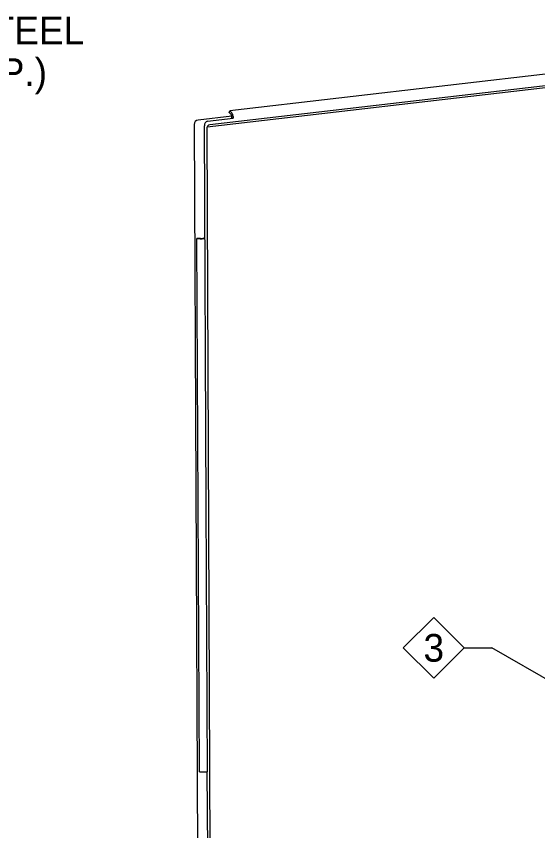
# Model space of a CAD drawing. Extents: x 99862 to 104211, y 98939 to 102076.
# Drawn here: x 101939.9 to 102241.1, y 100806.7 to 101277.4 of the extents above; entities that cross this region are included whole.
import ezdxf

# ---------------------------------------------------------------- set-up
doc = ezdxf.new("R2010")
doc.units = 0
for name, color, linetype in [('Level 15', 7, 'Continuous'), ('Level 20', 7, 'Continuous'), ('Level 3', 7, 'Continuous')]:
    doc.layers.add(name, color=color, linetype=linetype)

msp = doc.modelspace()

# ---------------------------------------------------------------- linework, layer by layer
at = {"layer": 'Level 15'}
for p in [(102198.54, 100912.37), (102270.4, 100880.12)]:
    msp.add_line(p, (102214.54, 100912.37), dxfattribs=at)
at = {"layer": 'Level 20'}
msp.add_lwpolyline([(102180.99, 100929.92), (102198.54, 100912.37), (102180.99, 100894.81), (102163.44, 100912.37)], close=True, dxfattribs=at)
at = {"layer": 'Level 3'}
for p, q in [((102286.89, 101248.73), (102063.28, 101222.66)), ((102303.87, 101242.9), (102050.13, 101213.32)), ((102309.36, 101244.74), (102051.67, 101214.7)), ((102062.88, 101221.85), (102063.28, 101222.66)), ((102063.93, 101220.73), (102062.88, 101221.85)), ((102063.28, 101222.66), (102064.32, 101221.54)), ((102064.37, 101219.65), (102044.86, 101217.37)), ((102050.34, 101216.76), (102065.11, 101218.49)), ((102064.38, 101218.57), (102064.38, 101219.47)), ((102065.11, 101218.49), (102064.38, 101218.57)), ((102065.1, 101219.39), (102065.11, 101218.49)), ((102042.65, 101214.88), (102044.62, 100776.47)), ((102049.54, 100994.87), (102048.55, 101214.07)), ((102049.88, 101212.01), (102051.83, 100778.04)), ((102044.47, 101148.99), (102044.24, 101148.87)), ((102044.24, 101148.87), (102046.01, 101148.83)), ((102045.64, 100840.65), (102044.24, 101148.87)), ((102046.23, 101148.95), (102044.47, 101148.99)), ((102048.11, 101149.06), (102047.55, 101149)), ((102048.84, 101148.98), (102048.11, 101149.06)), ((102048.28, 101148.91), (102048.84, 101148.98)), ((102049.63, 100994.75), (102049.54, 100994.87)), ((102050.33, 100840.77), (102049.63, 100994.75)), ((102045.64, 100840.65), (102047.41, 100840.61)), ((102049.68, 100840.69), (102050.33, 100840.77)), ((102050.52, 100775.67), (102050.23, 100840.76))]:
    msp.add_line(p, q, dxfattribs=at)
msp.add_arc((102045.15, 101214.89), 2.5, 96.6486, 180.2584, dxfattribs=at)
for centre, major_axis, ratio, start_param, end_param in [((102063.37, 101219.59), (0.17, -1.45), 0.688289, 1.409497, 2.391703), ((102063.37, 101219.59), (-0.29, 2.48), 0.688289, 4.551089, 5.533296), ((102050.35, 101214.28), (0.29, 2.48), 0.71602, 0.167679, 1.738476), ((102051.68, 101212.22), (-0.29, -2.48), 0.71602, 3.309272, 4.880068), ((102046.55, 101149.12), (-2.5, -0.01), 0.116476, 1.354282, 2.336488), ((102046.55, 101149.12), (1.46, 0.01), 0.116476, 4.495874, 5.478081), ((102047.94, 100840.9), (-2.5, -0.01), 0.116476, 1.354282, 2.336488)]:
    msp.add_ellipse(centre, major_axis=major_axis, ratio=ratio, start_param=start_param, end_param=end_param, dxfattribs=at)

# ---------------------------------------------------------------- texts
at = {"layer": 'Level 20'}
for s, p in [('STAINLESS STEEL', (101787.65, 101261.16)), ('CHANNEL (TYP.)', (101787.65, 101237.16)), ('3', (102175.09, 100904.37))]:
    msp.add_text(s, height=16, dxfattribs=at).set_placement(p)

doc.saveas('drawing.dxf')
